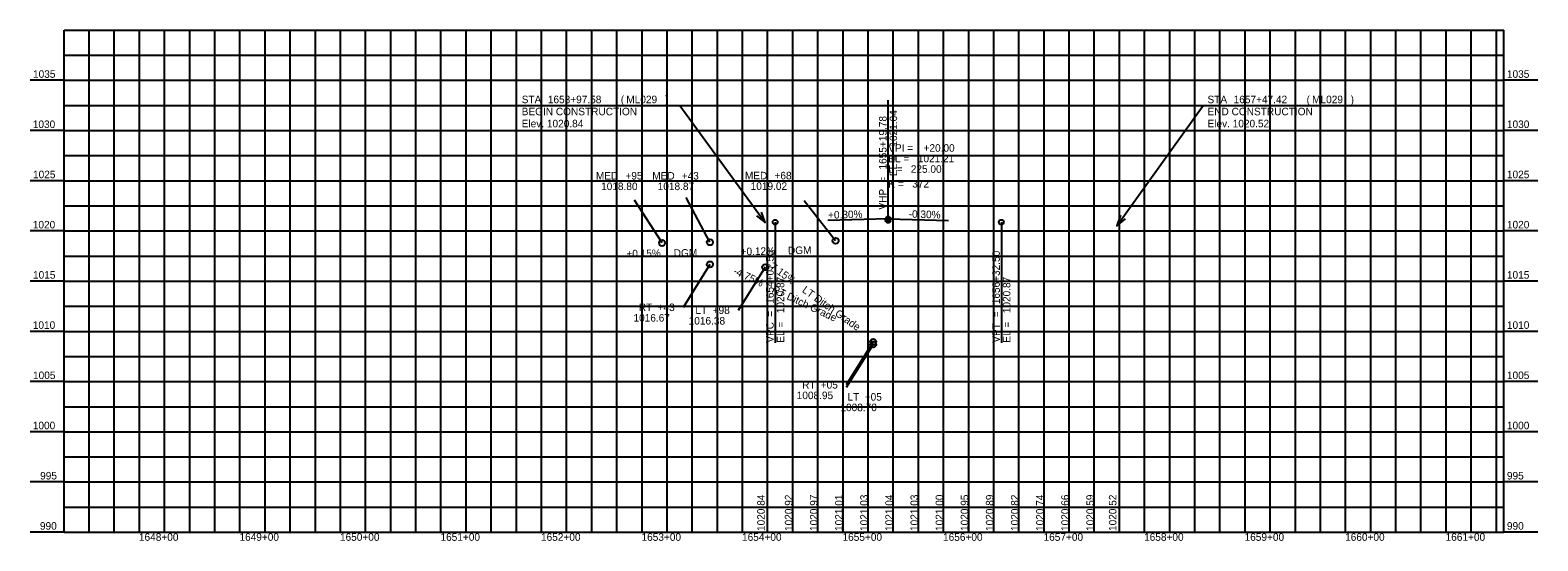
# Model space of a CAD drawing. Extents: x 4442 to 5942, y 981 to 1490.
import ezdxf

# ---------------------------------------------------------------- set-up
doc = ezdxf.new("R2010")
doc.units = 0
for name, color, linetype in [('ErosionControl', 7, 'Continuous'), ('Revetment', 7, 'Continuous'), ('SheetGridMajor', 7, 'Continuous'), ('SheetGridMinor', 7, 'Continuous'), ('Terrain', 7, 'Continuous'), ('Text', 7, 'Continuous')]:
    doc.layers.add(name, color=color, linetype=linetype)

msp = doc.modelspace()

# ---------------------------------------------------------------- linework, layer by layer
at = {"layer": 'ErosionControl'}
for p, q in [((4500.3, 990), (4500.3, 1490)), ((4525.3, 990), (4525.3, 1490)), ((4550.3, 990), (4550.3, 1490)), ((4600.3, 990), (4600.3, 1490)), ((4625.3, 990), (4625.3, 1490)), ((4650.3, 990), (4650.3, 1490)), ((4700.3, 990), (4700.3, 1490)), ((4725.3, 990), (4725.3, 1490)), ((4750.3, 990), (4750.3, 1490)), ((4800.3, 990), (4800.3, 1490)), ((4825.3, 990), (4825.3, 1490)), ((4850.3, 990), (4850.3, 1490)), ((4900.3, 990), (4900.3, 1490)), ((4925.3, 990), (4925.3, 1490)), ((4950.3, 990), (4950.3, 1490)), ((5000.3, 990), (5000.3, 1490)), ((5025.3, 990), (5025.3, 1490)), ((5050.3, 990), (5050.3, 1490)), ((5100.3, 990), (5100.3, 1490)), ((5125.3, 990), (5125.3, 1490)), ((5150.3, 990), (5150.3, 1490)), ((5200.3, 990), (5200.3, 1490)), ((5225.3, 990), (5225.3, 1490)), ((5250.3, 990), (5250.3, 1490)), ((5300.3, 990), (5300.3, 1490)), ((5325.3, 990), (5325.3, 1490)), ((5350.3, 990), (5350.3, 1490)), ((5400.3, 990), (5400.3, 1490)), ((5425.3, 990), (5425.3, 1490)), ((5450.3, 990), (5450.3, 1490)), ((5500.3, 990), (5500.3, 1490)), ((5525.3, 990), (5525.3, 1490)), ((5550.3, 990), (5550.3, 1490)), ((5600.3, 990), (5600.3, 1490)), ((5625.3, 990), (5625.3, 1490)), ((5650.3, 990), (5650.3, 1490)), ((5700.3, 990), (5700.3, 1490)), ((5725.3, 990), (5725.3, 1490)), ((5750.3, 990), (5750.3, 1490)), ((5800.3, 990), (5800.3, 1490)), ((5825.3, 990), (5825.3, 1490)), ((5850.3, 990), (5850.3, 1490)), ((5900.3, 990), (5900.3, 1490)), ((4475.3, 1465), (5907.8, 1465)), ((4475.3, 1415), (5907.8, 1415)), ((4475.3, 1365), (5907.8, 1365)), ((4475.3, 1315), (5907.8, 1315)), ((4475.3, 1265), (5907.8, 1265)), ((4475.3, 1215), (5907.8, 1215)), ((4475.3, 1165), (5907.8, 1165)), ((4475.3, 1115), (5907.8, 1115)), ((4475.3, 1065), (5907.8, 1065)), ((4475.3, 1015), (5907.8, 1015))]:
    msp.add_line(p, q, dxfattribs=at)
at = {"layer": 'Revetment'}
for p, q in [((5295.1, 1300.4), (5295.1, 1420.4)), ((5070.3, 1278), (5042.9, 1320.5)), ((5117.9, 1278.7), (5094.1, 1323.3)), ((5242.9, 1280.2), (5211.5, 1319.9)), ((5182.8, 1298.7), (5182.8, 1298.7)), ((5182.8, 1298.7), (5182.8, 1178.7)), ((5295.3, 1302.1), (5235.3, 1300.3)), ((5295.3, 1302.1), (5295.3, 1302.1)), ((5295.3, 1302.1), (5355.3, 1300.3)), ((5407.8, 1298.7), (5407.8, 1298.7)), ((5407.8, 1298.7), (5407.8, 1178.7)), ((5117.9, 1256.7), (5091.1, 1213.8)), ((5172.9, 1253.8), (5146.1, 1210.9)), ((5280.3, 1179.5), (5253.5, 1136.6)), ((5280.3, 1177), (5253.5, 1134.1))]:
    msp.add_line(p, q, dxfattribs=at)
for centre, radius in [((5295.1, 1300.4), 2.43), ((5070.3, 1278), 3), ((5117.9, 1278.7), 3), ((5242.9, 1280.2), 3), ((5117.9, 1256.7), 3), ((5172.9, 1253.8), 3), ((5280.3, 1179.5), 3), ((5280.3, 1177), 3)]:
    msp.add_circle(centre, radius, dxfattribs=at)
at = {"layer": 'SheetGridMajor'}
for p, q in [((4926.2, 1415), (5087.9, 1415)), ((5087.9, 1415), (5172.9, 1298.4)), ((5522.7, 1295.2), (5608.5, 1415)), ((5608.5, 1415), (5770.3, 1415))]:
    msp.add_line(p, q, dxfattribs=at)
for points in [[(5164.1, 1305.2), (5172.9, 1298.4), (5169.1, 1308.8)], [(5526.5, 1305.6), (5522.7, 1295.2), (5531.4, 1302.1)]]:
    msp.add_lwpolyline(points, dxfattribs=at)
for centre in [(5182.8, 1298.7), (5295.3, 1302.1), (5407.8, 1298.7)]:
    msp.add_circle(centre, 2.43, dxfattribs=at)
at = {"layer": 'Terrain'}
for p, q in [((4475.3, 1490), (5907.8, 1490)), ((4475.3, 990), (4475.3, 1490)), ((5907.8, 990), (5907.8, 1490)), ((4475.3, 990), (5907.8, 990))]:
    msp.add_line(p, q, dxfattribs=at)
at = {"layer": 'Text'}
for p, q in [((4575.3, 990), (4575.3, 1490)), ((4675.3, 990), (4675.3, 1490)), ((4775.3, 990), (4775.3, 1490)), ((4875.3, 990), (4875.3, 1490)), ((4975.3, 990), (4975.3, 1490)), ((5075.3, 990), (5075.3, 1490)), ((5175.3, 990), (5175.3, 1490)), ((5275.3, 990), (5275.3, 1490)), ((5375.3, 990), (5375.3, 1490)), ((5475.3, 990), (5475.3, 1490)), ((5575.3, 990), (5575.3, 1490)), ((5675.3, 990), (5675.3, 1490)), ((5775.3, 990), (5775.3, 1490)), ((5875.3, 990), (5875.3, 1490)), ((4475.3, 1440), (4441.6, 1440)), ((4475.3, 1440), (5907.8, 1440)), ((5941.6, 1440), (5907.8, 1440)), ((4475.3, 1390), (4441.6, 1390)), ((4475.3, 1390), (5907.8, 1390)), ((5941.6, 1390), (5907.8, 1390)), ((4475.3, 1340), (4441.6, 1340)), ((4475.3, 1340), (5907.8, 1340)), ((5941.6, 1340), (5907.8, 1340)), ((4475.3, 1290), (4441.6, 1290)), ((4475.3, 1290), (5907.8, 1290)), ((5941.6, 1290), (5907.8, 1290)), ((4475.3, 1240), (4441.6, 1240)), ((4475.3, 1240), (5907.8, 1240)), ((5941.6, 1240), (5907.8, 1240)), ((4475.3, 1190), (4441.6, 1190)), ((4475.3, 1190), (5907.8, 1190)), ((5941.6, 1190), (5907.8, 1190)), ((4475.3, 1140), (4441.6, 1140)), ((4475.3, 1140), (5907.8, 1140)), ((5941.6, 1140), (5907.8, 1140)), ((4475.3, 1090), (4441.6, 1090)), ((4475.3, 1090), (5907.8, 1090)), ((5941.6, 1090), (5907.8, 1090)), ((4475.3, 1040), (4441.6, 1040)), ((4475.3, 1040), (5907.8, 1040)), ((5941.6, 1040), (5907.8, 1040)), ((4475.3, 990), (4441.6, 990)), ((5941.6, 990), (5907.8, 990))]:
    msp.add_line(p, q, dxfattribs=at)

# ---------------------------------------------------------------- texts
at = {"layer": 'Revetment'}
for s, p in [('1035', (4444.4, 1442.5)), ('1035', (5910.8, 1442.5)), ('1030', (4444.2, 1392.5)), ('1030', (5910.8, 1392.5)), ('VPI = ', (5295.3, 1368.9)), ('EL = ', (5295.3, 1358.4)), ('1021.21', (5324.7, 1358.4)), ('+20.00', (5330.4, 1368.9)), ('1025', (4444.4, 1342.5)), ('L = ', (5295.3, 1347.9)), ("225.00'", (5317.7, 1347.9)), ('1025', (5910.8, 1342.5)), ('MED ', (5152.7, 1341.4)), ('1019.02', (5158.4, 1330.9)), ('+68', (5182.1, 1341.4)), ('K = ', (5295.3, 1333.2)), ('372', (5319.1, 1333.2)), ('1020', (4444.2, 1292.5)), ('1020', (5910.8, 1292.5)), ('1015', (4444.4, 1242.5)), ('1015', (5910.8, 1242.5)), ('RT ', (5047.2, 1210.2)), ('+43', (5065.8, 1210.2)), ('1010', (4444.2, 1192.5)), ('1016.67', (5041.8, 1199.7)), ('1016.38', (5096.7, 1196.8)), ('LT ', (5103.4, 1207.3)), ('+98', (5120.6, 1207.3)), ('1010', (5910.8, 1192.5)), ('1005', (4444.4, 1142.5)), ('RT ', (5209.6, 1133)), ('+05', (5228.1, 1133)), ('1005', (5910.8, 1142.5)), ('1008.95', (5204.2, 1122.5)), ('LT ', (5254.7, 1121)), ('+05', (5271.9, 1121)), ('1008.70', (5247.7, 1110.5)), ('1000', (4444.2, 1092.5)), ('1000', (5910.8, 1092.5)), ('995', (4451.5, 1042.5)), ('995', (5910.8, 1042.5)), ('990', (4451.3, 992.5)), ('990', (5910.8, 992.5)), ('1648+00', (4549.8, 981.4)), ('1649+00', (4649.8, 981.4)), ('1650+00', (4749.8, 981.4)), ('1651+00', (4849.8, 981.4)), ('1652+00', (4949.8, 981.4)), ('1653+00', (5049.8, 981.4)), ('1654+00', (5149.8, 981.4)), ('1655+00', (5249.8, 981.4)), ('1656+00', (5349.8, 981.4)), ('1657+00', (5449.8, 981.4)), ('1658+00', (5549.8, 981.4)), ('1659+00', (5649.8, 981.4)), ('1660+00', (5749.8, 981.4)), ('1661+00', (5849.8, 981.4))]:
    msp.add_text(s, height=7.5, dxfattribs=at).set_placement(p)
for s, rotation, p in [('1655+19.78', 90, (5293.6, 1351.2)), ('1021.04', 90, (5304.1, 1374)), ('EL = ', 90, (5304.1, 1344.6)), (' = ', 90, (5293.6, 1335.4)), ('VHP', 90, (5293.6, 1311.3)), ('+0.30%', 1.7312, (5235.5, 1302.1)), ('-0.30%', 358.2622, (5315.5, 1303.3)), ('1654+07.50', 90, (5181.3, 1217.5)), ('1656+32.50', 90, (5406.3, 1217)), ('-4.75%', 334.5877, (5140.3, 1247.7)), ('-7.15%', 324.4195, (5174.2, 1254.6)), (' RT Ditch Grade', 334.5877, (5176.4, 1230.5)), ('1020.87', 90, (5191.8, 1208.1)), (' LT Ditch Grade', 324.4195, (5206.7, 1231.3)), ('1020.87', 90, (5416.8, 1208.1)), (' = ', 90, (5181.3, 1201.8)), (' = ', 90, (5406.3, 1201.2)), ('VPC', 90, (5181.3, 1178.7)), ('EL = ', 90, (5191.8, 1178.7)), ('VPT', 90, (5406.3, 1178.7)), ('EL = ', 90, (5416.8, 1178.7))]:
    msp.add_text(s, height=7.5, rotation=rotation, dxfattribs=at).set_placement(p)
at = {"layer": 'SheetGridMajor'}
for s, rotation, p in [(' (', 0, (5026.4, 1417.2)), (')', 0, (5073, 1417.2)), (' (', 0, (5708.7, 1417.2)), (')', 0, (5755.3, 1417.2)), ('STA ', 0, (4930.6, 1417.2)), ('BEGIN CONSTRUCTION', 0, (4930.6, 1405.2)), ('1653+97.58', 0, (4956.6, 1417.2)), ('ML029', 0, (5034.7, 1417.2)), ('STA ', 0, (5612.9, 1417.2)), ('END CONSTRUCTION', 0, (5612.9, 1405.2)), ('1657+47.42', 0, (5638.9, 1417.2)), ('ML029', 0, (5717, 1417.2)), ('Elev. 1020.84', 0, (4930.6, 1393.2)), ('Elev. 1020.52', 0, (5612.9, 1393.2)), ('1020.84', 90, (5172.4, 991.2)), ('1020.92', 90, (5199.9, 991.2)), ('1020.97', 90, (5224.9, 991.2)), ('1021.01', 90, (5249.9, 991.2)), ('1021.03', 90, (5274.9, 991.2)), ('1021.04', 90, (5299.9, 991.2)), ('1021.03', 90, (5324.9, 991.2)), ('1021.00', 90, (5349.9, 991.2)), ('1020.95', 90, (5374.9, 991.2)), ('1020.89', 90, (5399.9, 991.2)), ('1020.82', 90, (5424.9, 991.2)), ('1020.74', 90, (5449.9, 991.2)), ('1020.66', 90, (5474.9, 991.2)), ('1020.59', 90, (5499.9, 991.2)), ('1020.52', 90, (5522.3, 991.2))]:
    msp.add_text(s, height=7.5, rotation=rotation, dxfattribs=at).set_placement(p)
at = {"layer": 'SheetGridMinor'}
for s, rotation, p in [('MED ', 360, (5004.4, 1341.2)), ('1018.80', 360, (5009.6, 1330.7)), ('+95', 360, (5033.8, 1341.2)), ('MED ', 359.9333, (5060.5, 1341.2)), ('1018.87', 359.9333, (5065.9, 1330.7)), ('+43', 359.9333, (5089.8, 1341.2)), ('+0.15%', 0.8611, (5034.8, 1263.6)), (' DGM', 0.8611, (5079.1, 1264.2)), ('+0.12%', 1.3016, (5148.5, 1265.7)), (' DGM', 1.3016, (5192.8, 1266.7))]:
    msp.add_text(s, height=7.5, rotation=rotation, dxfattribs=at).set_placement(p)

doc.saveas('drawing.dxf')
